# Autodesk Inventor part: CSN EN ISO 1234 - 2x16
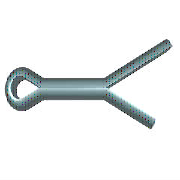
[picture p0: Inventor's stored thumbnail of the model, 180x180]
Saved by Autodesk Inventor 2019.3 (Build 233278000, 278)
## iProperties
Created: 2018-01
Part Number: CSN EN ISO 1234 - 2x16
Material: Ocel
Description: Závlačka
Document SubType Name: Modeling
Standard: CSN EN ISO 1234
Designer: B-hon
Standards Organization: CSN
Language: cs-CZ
Size Designation: 2x16
Categories: <MemberInstance><Categories><Category DisplayName="Spojovací materiál" InternalName="e4da775c-781d-43d5-af7c-5136215cf5a6" Mnemonic="FSTN"><Category DisplayName
Density: 7.85 g/cm^3
Sheet Metal Rule: Výchozí
Appearance: Plech
IsCustomPart: 0
Author: B-hon
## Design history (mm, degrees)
node "MSC_PF1"
node "MSC_A1"
node "MSC_PT1"
node "IDS_WORKPLANE{1}"
body "Solid1"
sketch "Náčrt1"
  geometry: L1 (5, 1)-(-5, 1); L2 (-5, 1)-(-6.476, 1.648); L3 (-6.476, -1.648)-(-5, -1); L4 (-5, -1)-(5, -1); L5 (5, -0.01)-(-5.208, -0.01); L6 (-5.208, -0.01)-(-6.874, -0.742); L7 (-6.874, 0.742)-(-5.208, 0.01); L8 (-5.208, 0.01)-(5, 0.01); L9 (10.011, 3.513)-(11, 4.01); L10 (11, 4.01)-(10.804, 2.921); L11 (13.89, -4.909)-(14, -6.01); L12 (13.053, -5.437)-(14, -6.01); L13 (-49.8, 0)-(53.8, 0) reference; L14 (5, 1)-(5, 0.01); L15 (5, -0.01)-(5, -1); L16 (-9, 0)-(-9, 15.609); L17 (-6.476, 1.648)-(-6.874, 0.742); L18 (10.011, 3.513)-(10.804, 2.921); L19 (10.408, 3.217)-(11, 4.01); L20 (13.89, -4.909)-(13.053, -5.437); L21 (13.471, -5.173)-(14, -6.01); L22 (-5, -1)-(5, 1); A1 r 1.8 centre (-7.2, 0) between (-6.476, 1.648) and (-6.476, -1.648); A2 r 0.81 centre (-7.2, 0) between (-6.874, 0.742) and (-6.874, -0.742); A3 r 6.253 centre (5, 7.253) between (5, 1) and (10.011, 3.513); A4 r 7.243 centre (5, 7.253) between (5, 0.01) and (10.804, 2.921); A5 r 10.515 centre (5, -10.525) between (13.89, -4.909) and (5, -0.01); A6 r 9.525 centre (5, -10.525) between (13.053, -5.437) and (5, -1); 3 further points
  constraints: 42 end point, 13 point on circle, 9 tangent, 6 centre point, 6 parallel, 5 equal length, 5 vertical alignment, 3 concentric, 3 midpoint, 3 perpendicular, 2 point on line, 1 collinear, 1 horizontal, 1 other
  dimensions: "d1" = 6 horizontal distance of L9.end A3.centre (= v); "d2" = 4 vertical distance of L9.end L8.end (= 0.666667 x d1); "d10" = 3.6 diameter of A1 (= ParC); "d11" = 2 distance between parallel lines of L4 L1 (= Diam); "d12" = 0.99 distance of L5.start L4.end (computed from d11); "d13" = 4 distance from line of L3.end L16 (= b); "d15" = 10 distance of L4.end L3.end (= prf_lf); "d16" = 6 distance from line of L5 L11.end (= 1.5 x d2); "d17" = 9 horizontal distance of L11.end A5.centre (= 1.5 x d1); "d26" = 0.99 distance of L2.end L7.start (= d12)
extrude "Vysunutí1" new body sketch "Náčrt1" stored distance "d18" = 2 (= Diam); taper "d19" = 0 deg
fillet "Zaoblení1" dims "d20" = 0.99 (= d12)
other parameters: "msp_Thickness" = 0.5, "msp_BendRadius" = 0.5 (= msp_Thickness), "msp_BendReliefWidth" = 0.5 (= msp_Thickness), "msp_BendReliefDepth" = 0.25 (= 0.5 x msp_Thickness), "msp_CornerReliefSize" = 2 (= 4 x msp_Thickness), "SeamGap" = 0.01, "msp_MinimumRemnant" = 1 (= 2 x msp_Thickness), "msp_TransitionRadius" = 0.5 (= msp_BendRadius), "b" = 4 [user parameter; used in 1 equation term], "ParC" = 3.6 [user parameter; used in 1 equation term], "Diam" = 2 [user parameter; used in 2 equation terms], "v" = 6 [user parameter; used in 1 equation term], "d27" = 0, "prf_lf" = 10 [user parameter; used in 1 equation term], "d32" = 0, "d33" = 0, "d34" = 0, "JacobiRadiusSize" = 0.5 (= msp_Thickness), "GapSize" = 0.5 (= msp_Thickness)
